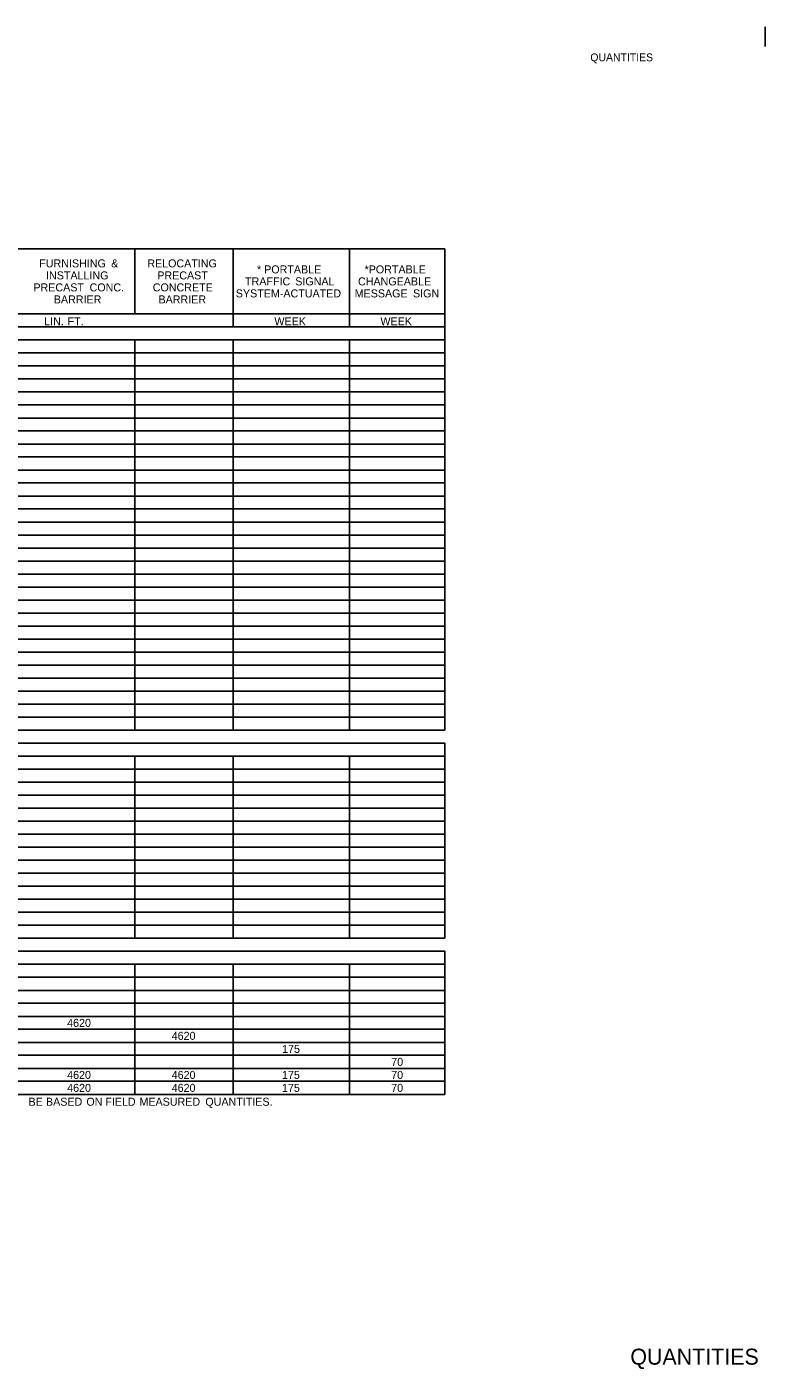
# Model space of a CAD drawing. Extents: x 544250 to 1930787, y -1948365 to 596640.
# Drawn here: x 545241 to 545794, y -1947044 to -1946038 of the extents above; entities that cross this region are included whole.
import ezdxf

# ---------------------------------------------------------------- set-up
doc = ezdxf.new("R2010")
doc.units = 0
for name, color, linetype in [('Default', 7, 'Continuous'), ('R_Border', 7, 'Continuous'), ('R_Border Prem', 7, 'Continuous')]:
    doc.layers.add(name, color=color, linetype=linetype)

msp = doc.modelspace()

# ---------------------------------------------------------------- linework, layer by layer
at = {"layer": 'Default'}
for p, q in [((545794.3, -1946038.1), (545794.3, -1946052.8)), ((544454.4, -1946204.5), (545554.2, -1946204.5)), ((545321.7, -1946253.3), (545321.7, -1946204.5)), ((545395.3, -1946263), (545395.3, -1946204.5)), ((545482.5, -1946204.5), (545554.2, -1946204.5)), ((545482.5, -1946263), (545482.5, -1946204.5)), ((545554.2, -1946565.3), (545554.2, -1946204.5)), ((544980.9, -1946253.3), (545554.2, -1946253.3)), ((545190, -1946253.3), (545554.2, -1946253.3)), ((545482.5, -1946263), (545482.5, -1946253.3)), ((544454.4, -1946263), (545554.2, -1946263)), ((544922.9, -1946263), (545554.2, -1946263)), ((544454.4, -1946272.8), (545554.2, -1946272.8)), ((545321.7, -1946565.3), (545321.7, -1946272.8)), ((545321.7, -1946565.3), (545321.7, -1946272.8)), ((545395.3, -1946565.3), (545395.3, -1946272.8)), ((545395.3, -1946565.3), (545395.3, -1946272.8)), ((545482.5, -1946565.3), (545482.5, -1946272.8)), ((544454.4, -1946282.5), (545554.2, -1946282.5)), ((544454.4, -1946292.3), (545554.2, -1946292.3)), ((544454.4, -1946302), (545554.2, -1946302)), ((544454.4, -1946311.8), (545554.2, -1946311.8)), ((544454.4, -1946321.5), (545554.2, -1946321.5)), ((544454.4, -1946331.3), (545554.2, -1946331.3)), ((544454.4, -1946341), (545554.2, -1946341)), ((544454.4, -1946350.8), (545554.2, -1946350.8)), ((544454.4, -1946360.5), (545554.2, -1946360.5)), ((544454.4, -1946370.3), (545554.2, -1946370.3)), ((544454.4, -1946380), (545554.2, -1946380)), ((544454.4, -1946389.8), (545554.2, -1946389.8)), ((544454.4, -1946399.5), (545554.2, -1946399.5)), ((544454.4, -1946409.3), (545554.2, -1946409.3)), ((544454.4, -1946419), (545554.2, -1946419)), ((544454.4, -1946428.8), (545554.2, -1946428.8)), ((544454.4, -1946438.5), (545554.2, -1946438.5)), ((544454.4, -1946448.3), (545554.2, -1946448.3)), ((544454.4, -1946458), (545554.2, -1946458)), ((544454.4, -1946467.8), (545554.2, -1946467.8)), ((544454.4, -1946477.5), (545554.2, -1946477.5)), ((544454.4, -1946487.3), (545554.2, -1946487.3)), ((544454.4, -1946497), (545554.2, -1946497)), ((544454.4, -1946506.8), (545554.2, -1946506.8)), ((544454.4, -1946516.5), (545554.2, -1946516.5)), ((544454.4, -1946526.3), (545554.2, -1946526.3)), ((544454.4, -1946536), (545554.2, -1946536)), ((544454.4, -1946545.8), (545554.2, -1946545.8)), ((544454.4, -1946555.5), (545554.2, -1946555.5)), ((544454.4, -1946555.5), (545554.2, -1946555.5)), ((545482.5, -1946565.3), (545482.5, -1946555.5)), ((544454.4, -1946565.3), (545554.2, -1946565.3)), ((544454.4, -1946575), (545554.2, -1946575)), ((544454.4, -1946575), (545554.2, -1946575)), ((545554.2, -1946721.3), (545554.2, -1946575)), ((544454.4, -1946584.8), (545554.2, -1946584.8)), ((545321.7, -1946721.3), (545321.7, -1946584.8)), ((545321.7, -1946721.3), (545321.7, -1946584.8)), ((545395.3, -1946721.3), (545395.3, -1946584.8)), ((545395.3, -1946721.3), (545395.3, -1946584.8)), ((545482.5, -1946721.3), (545482.5, -1946584.8)), ((544454.4, -1946594.5), (545554.2, -1946594.5)), ((544454.4, -1946604.3), (545554.2, -1946604.3)), ((544454.4, -1946614), (545554.2, -1946614)), ((544454.4, -1946623.8), (545554.2, -1946623.8)), ((544454.4, -1946633.5), (545554.2, -1946633.5)), ((544454.4, -1946643.3), (545554.2, -1946643.3)), ((544454.4, -1946653), (545554.2, -1946653)), ((544454.4, -1946662.8), (545554.2, -1946662.8)), ((544454.4, -1946672.5), (545554.2, -1946672.5)), ((544454.4, -1946682.3), (545554.2, -1946682.3)), ((544454.4, -1946692), (545554.2, -1946692)), ((544454.4, -1946701.8), (545554.2, -1946701.8)), ((544454.4, -1946711.5), (545554.2, -1946711.5)), ((544454.4, -1946711.5), (545554.2, -1946711.5)), ((545482.5, -1946721.3), (545482.5, -1946711.5)), ((544454.4, -1946721.3), (545554.2, -1946721.3)), ((544454.4, -1946731), (545554.2, -1946731)), ((544454.4, -1946731), (545554.2, -1946731)), ((545554.2, -1946838.3), (545554.2, -1946731)), ((544454.4, -1946740.8), (545554.2, -1946740.8)), ((545321.7, -1946838.3), (545321.7, -1946740.8)), ((545321.7, -1946838.3), (545321.7, -1946740.8)), ((545395.3, -1946779.8), (545395.3, -1946740.8)), ((545395.3, -1946838.3), (545395.3, -1946740.8)), ((545482.5, -1946838.3), (545482.5, -1946740.8)), ((544454.4, -1946750.5), (545554.2, -1946750.5)), ((544454.4, -1946760.3), (545554.2, -1946760.3)), ((544454.4, -1946770), (545554.2, -1946770)), ((544454.4, -1946779.8), (545554.2, -1946779.8)), ((544454.4, -1946789.5), (545554.2, -1946789.5)), ((545238.3, -1946789.5), (545554.2, -1946789.5)), ((545395.3, -1946838.3), (545395.3, -1946789.5)), ((544454.4, -1946799.3), (545554.2, -1946799.3)), ((544454.4, -1946809), (545554.2, -1946809)), ((545482.5, -1946818.8), (545482.5, -1946809)), ((544454.4, -1946818.8), (545554.2, -1946818.8)), ((544980.9, -1946818.8), (545554.2, -1946818.8)), ((544454.4, -1946828.5), (545554.2, -1946828.5)), ((544454.4, -1946838.3), (545554.2, -1946838.3))]:
    msp.add_line(p, q, dxfattribs=at)

# ---------------------------------------------------------------- texts
for s, p in [('FURNISHING', (545250, -1946218.4)), (' &', (545301.7, -1946218.4)), ('RELOCATING', (545331, -1946218.4)), ('INSTALLING', (545255.1, -1946227.4)), ('PRECAST', (545338.5, -1946227.4)), ('*', (545413.3, -1946222.9)), (' PORTABLE', (545416.4, -1946222.9)), ('*PORTABLE', (545493.9, -1946222.9)), ('PRECAST', (545245.6, -1946236.4)), (' CONC.', (545285.5, -1946236.4)), ('CONCRETE', (545335.1, -1946236.4)), ('TRAFFIC', (545404.3, -1946231.9)), (' SIGNAL', (545439.7, -1946231.9)), ('CHANGEABLE', (545489, -1946231.9)), ('BARRIER', (545260.9, -1946245.4)), ('BARRIER', (545339.4, -1946245.4)), ('SYSTEM-ACTUATED', (545397.4, -1946240.9)), ('MESSAGE', (545486.5, -1946240.9)), (' SIGN', (545528, -1946240.9)), ('LIN.', (545253.7, -1946261.8)), (' FT.', (545269, -1946261.8)), ('WEEK', (545426.3, -1946261.8)), ('WEEK', (545505.8, -1946261.8)), ('4620', (545270.9, -1946787.7)), ('4620', (545349.3, -1946797.4)), ('175', (545432.1, -1946807.2)), ('70', (545513.9, -1946816.9)), ('4620', (545270.9, -1946826.7)), ('4620', (545349.3, -1946826.7)), ('175', (545432, -1946826.7)), ('70', (545513.9, -1946826.7)), ('4620', (545270.9, -1946836.4)), ('4620', (545349.3, -1946836.4)), ('175', (545432, -1946836.4)), ('70', (545513.9, -1946836.4)), (' BE', (545239.7, -1946846.8)), (' BASED', (545252.8, -1946846.8)), (' ON', (545283.1, -1946846.8)), (' FIELD', (545297.3, -1946846.8)), (' MEASURED', (545322.9, -1946846.8)), (' QUANTITIES.', (545372.3, -1946846.8))]:
    msp.add_text(s, height=6, dxfattribs=at).set_placement(p)
at = {"layer": 'R_Border'}
msp.add_text('QUANTITIES', height=12, rotation=360, dxfattribs=at).set_placement((545693.2, -1947040.9))
at = {"layer": 'R_Border Prem'}
msp.add_text('QUANTITIES', height=5.86, rotation=360, dxfattribs=at).set_placement((545663.2, -1946063.9))

doc.saveas('drawing.dxf')
